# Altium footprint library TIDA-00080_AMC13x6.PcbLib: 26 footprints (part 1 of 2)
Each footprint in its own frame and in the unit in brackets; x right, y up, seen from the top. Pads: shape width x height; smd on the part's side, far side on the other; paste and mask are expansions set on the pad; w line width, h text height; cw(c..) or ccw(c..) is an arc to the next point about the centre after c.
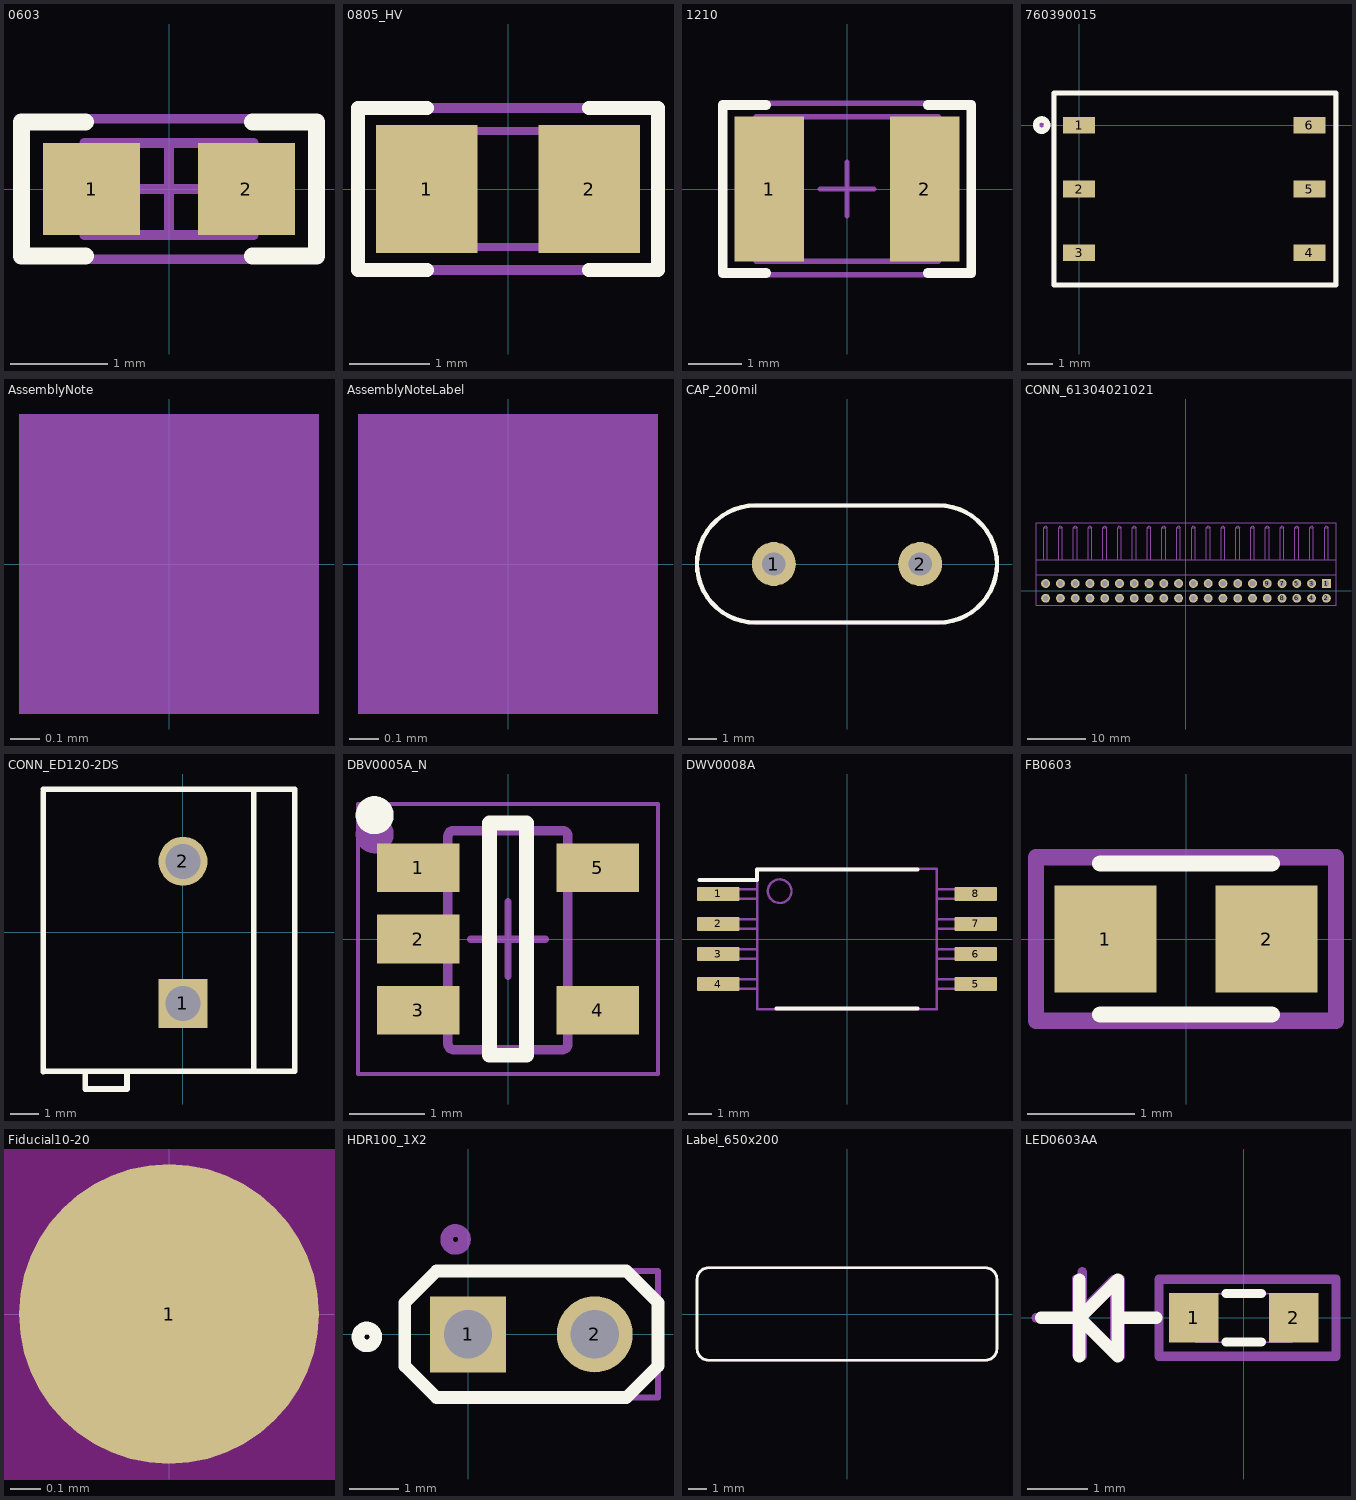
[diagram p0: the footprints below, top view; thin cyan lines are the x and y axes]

## 0603 [mm] "0603 from SM-752 data"
height 0.85
pads (2):
  rect 1x0.95 smd: 1(-0.8,0) 2(0.8,0)
Top Overlay:
  lines w0.178: -0.864,-0.691 -1.524,-0.691 -1.524,0.693 -0.864,0.693 ; 0.864,-0.691 1.524,-0.691 1.524,0.693 0.864,0.693
Mechanical 5:
  lines w0.1: -1.55,-0.725 -1.55,0.725 1.55,0.725 1.55,-0.725 -1.55,-0.725
  text ".Designator" at 0.881,0.412 h0.64
Mechanical 13:
  lines w0.1: -0.55,-0.475 -0.55,0.475 ; 0.55,-0.475 0.55,0.475 ; -0.875,-0.475 0.875,-0.475 0.875,0.475 -0.875,0.475 -0.875,-0.475
Mechanical 15:
  lines w0.1: -0.475,0 0.475,0 ; 0,-0.475 0,0.475 ; -1.55,-0.725 1.55,-0.725 1.55,0.725 -1.55,0.725 -1.55,-0.725
3D body: height 0.85, standoff 0, extent -0.874,-0.474 -0.551,0.474
3D body: height 0.85, standoff 0, extent -0.549,-0.474 0.549,0.474
3D body: height 0.85, standoff 0, extent 0.551,-0.474 0.874,0.474

## 0805_HV [mil] "0805 with 30mil clearance between pads"
height 43.31
pads (2):
  rect 50x63 smd: 1(-40,0) 2(40,0)
Top Overlay:
  lines w7: -40,-40 -74,-40 -74,0 -74,40 -40,40 ; 40,-40 74,-40 74,0 74,40 40,40
Mechanical 5:
  lines w5: -74,-40 -74,40 74,40 74,-40 -74,-40
  text ".Designator" at -25.11,-12.92 h25
Mechanical 13:
  lines w3.94: -25.59,-28.54 -25.59,28.54 ; 25.59,-28.54 25.59,28.54 ; -43.31,-28.54 43.31,-28.54 43.31,28.54 -43.31,28.54 -43.31,-28.54
3D body: height 43.31, standoff 0, extent -43.29,-28.52 -25.61,28.52
3D body: height 43.31, standoff 0, extent -25.57,-28.52 25.57,28.52
3D body: height 43.31, standoff 0, extent 25.61,-28.52 43.29,28.52

## 1210 [mm] "1210 from SM-752 data"
height 1.35
pads (2):
  rect 1.3x2.7 smd: 1(-1.45,0) 2(1.45,0)
Top Overlay:
  lines w0.178: -1.511,-1.568 -2.316,-1.568 -2.316,1.568 -1.511,1.568 ; 1.511,-1.568 2.316,-1.568 2.316,1.568 1.511,1.568
Mechanical 5:
  lines w0.1: -1.7,-1.35 -1.7,1.35 1.7,1.35 1.7,-1.35 -1.7,-1.35
  text ".Designator" at -1.03,-0.443 h0.64
Mechanical 13:
  lines w0.1: -1.2,-1.35 -1.2,1.35 ; 1.2,-1.35 1.2,1.35 ; -1.7,-1.35 1.7,-1.35 1.7,1.35 -1.7,1.35 -1.7,-1.35
Mechanical 15:
  lines w0.1: -0.5,0 0.5,0 ; 0,-0.5 0,0.5 ; -2.35,-1.6 2.35,-1.6 2.35,1.6 -2.35,1.6 -2.35,-1.6
3D body: height 1.35, standoff 0, extent 1.201,-1.349 1.699,1.349
3D body: height 1.35, standoff 0, extent -1.199,-1.349 1.199,1.349
3D body: height 1.35, standoff 0, extent -1.699,-1.349 -1.201,1.349

## 760390015 [mm]
pads (6):
  rect 1.27x0.66 smd: 1(0,0) 2(0,-2.54) 3(0,-5.08) 4(9.14,-5.08) 5(9.14,-2.54) 6(9.14,0)
Top Overlay:
  circle w0.254: c-1.494,0 r0.224
  lines w0.2: -1,-6.35 -1,1.27 10.2,1.27 10.2,-6.35 -1,-6.35
Mechanical 5:
  circle w0.254: c-1.397,0 r0.127
  lines w0.152: -1.016,-6.35 10.16,-6.35 10.16,1.27 -1.016,1.27 -1.016,-6.35
  text ".designator" at 4.007,0.303 h0.64
3D body: height 4.2, standoff 0.2, extent -1,-6.4 10.2,1.2

## AssemblyNote [mil] "Assembly Note"
Mechanical 5:
  rectangle: -20,-20 20,20
  text ".Designator" at -165,-20 h30
  text ".Comment" at 45,-20 h30

## AssemblyNoteLabel [mil] "Assembly Note for PCB Labels"
Mechanical 5:
  rectangle: -20,-20 20,20
  text ".Designator" at -165,-20 h30
  text "Install label in silkscreened box after final wash.  Text shall be 8 pt font.  Text shall be per the Label Table in the PDF schematic." at 45,-20 h30

## CAP_200mil [mil]
pads (2):
  round 60 hole 32 mask+5: 1(-100,0) 2(100,0)
Top Overlay:
  lines w6: -125,-80 cw(c-125,0) -125,80 125,80 cw(c125,0) 125,-80 -125,-80
Mechanical 5:
  lines w5: -125,-80 cw(c-125,0) -125,80 125,80 cw(c125,0) 125,-80 -125,-80
  text ".Designator" at -39,-17 h25

## CONN_61304021021 [mil]
pads (40):
  rect 60x60 hole 38: 1(952,50)
  round 60 hole 38: 2(952,-50) 3(852,50) 4(852,-50) 5(752,50) 6(752,-50) 7(652,50) 8(652,-50) 9(552,50) 10(552,-50) 11(452,50) 12(452,-50) 13(352,50) 14(352,-50) 15(252,50) 16(252,-50) 17(152,50) 18(152,-50) 19(52,50) 20(52,-50) 21(-48,50) 22(-48,-50) 23(-148,50) 24(-148,-50) 25(-248,50) 26(-248,-50) 27(-348,50) 28(-348,-50) 29(-448,50) 30(-448,-50) 31(-548,50) 32(-548,-50) 33(-648,50) 34(-648,-50) 35(-748,50) 36(-748,-50) 37(-848,50) 38(-848,-50) 39(-948,50) 40(-948,-50)
Mechanical 5:
  lines w5: -1013,109.5 1017,109.5 ; -1013,209.5 1017,209.5 ; -1013,-95.5 1017,-95.5 1017,459.5 -1013,459.5 -1013,-95.5
  text ".Designator" at 42.01,13.69 h25
Mechanical 16:
  lines w1: -960.5,210 -960.5,427.5 ; -935.5,210 -935.5,427.5 ; -860.5,210 -860.5,427.5 ; -835.5,210 -835.5,427.5 ; -760.5,210 -760.5,427.5 ; -735.5,210 -735.5,427.5 ; -660.5,210 -660.5,427.5 ; -635.5,210 -635.5,427.5 ; -560.5,210 -560.5,427.5 ; -535.5,210 -535.5,427.5 ; -460.5,210 -460.5,427.5 ; -435.5,210 -435.5,427.5 ; -360.5,210 -360.5,427.5 ; -335.5,210 -335.5,427.5 ; -260.5,210 -260.5,427.5 ; -235.5,210 -235.5,427.5 ; -160.5,210 -160.5,427.5 ; -135.5,210 -135.5,427.5 ; -60.5,210 -60.5,427.5 ; -35.5,210 -35.5,427.5 ; 39.5,210 39.5,427.5 ; 64.5,210 64.5,427.5 ; 139.5,210 139.5,427.5 ; 164.5,210 164.5,427.5 ; 239.5,210 239.5,427.5 ; 264.5,210 264.5,427.5 ; 339.5,210 339.5,427.5 ; 364.5,210 364.5,427.5 ; 439.5,210 439.5,427.5 ; 464.5,210 464.5,427.5 ; 539.5,210 539.5,427.5 ; 564.5,210 564.5,427.5 ; 639.5,210 639.5,427.5 ; 664.5,210 664.5,427.5 ; 739.5,210 739.5,427.5 ; 764.5,210 764.5,427.5 ; 839.5,210 839.5,427.5 ; 864.5,210 864.5,427.5 ; 939.5,210 939.5,427.5 ; 964.5,210 964.5,427.5 ; -960.5,427.5 -948,440 -935.5,427.5 ; -960.5,427.5 -935.5,427.5 ; -860.5,427.5 -835.5,427.5 ; -860.5,427.5 -848,440 -835.5,427.5 ; -760.5,427.5 -748,440 -735.5,427.5 ; -760.5,427.5 -735.5,427.5 ; -660.5,427.5 -648,440 -635.5,427.5 ; -660.5,427.5 -635.5,427.5 ; -560.5,427.5 -548,440 -535.5,427.5 ; -560.5,427.5 -535.5,427.5 ; -460.5,427.5 -435.5,427.5 ; -460.5,427.5 -448,440 -435.5,427.5 ; -360.5,427.5 -348,440 -335.5,427.5 ; -360.5,427.5 -335.5,427.5 ; -260.5,427.5 -248,440 -235.5,427.5 ; -260.5,427.5 -235.5,427.5 ; -160.5,427.5 -148,440 -135.5,427.5 ; -160.5,427.5 -135.5,427.5 ; -60.5,427.5 -48,440 -35.5,427.5 ; -60.5,427.5 -35.5,427.5 ; 39.5,427.5 64.5,427.5 ; 39.5,427.5 52,440 64.5,427.5 ; 139.5,427.5 164.5,427.5 ; 139.5,427.5 152,440 164.5,427.5 ; 239.5,427.5 264.5,427.5 ; 239.5,427.5 252,440 264.5,427.5 ; 339.5,427.5 352,440 364.5,427.5 ; 339.5,427.5 364.5,427.5 ; 439.5,427.5 452,440 464.5,427.5 ; 439.5,427.5 464.5,427.5 ; 539.5,427.5 552,440 564.5,427.5 ; 539.5,427.5 564.5,427.5 ; 639.5,427.5 652,440 664.5,427.5 ; 639.5,427.5 664.5,427.5 ; 739.5,427.5 752,440 764.5,427.5 ; 739.5,427.5 764.5,427.5 ; 839.5,427.5 852,440 864.5,427.5 ; 839.5,427.5 864.5,427.5 ; 939.5,427.5 952,440 964.5,427.5 ; 939.5,427.5 964.5,427.5

## CONN_ED120-2DS [mm] "ONSHORE"
height 13
pads (2):
  rect 1.75x1.75 hole 1.25: 1(0,-2.54)
  round 1.75 hole 1.25: 2(0,2.54)
Top Overlay:
  lines w0.2: -5,-4.985 -5,5.015 ; -5,-4.96 4,-4.96 ; -5,5.115 4,5.115 4,-4.885 ; -3.5,-4.96 -3.5,-5.6 -2,-5.6 -2,-4.96 ; 2.525,-4.95 2.525,5.05
Mechanical 5:
  lines w0.1: -5,-4.96 4,-4.96 ; -5,-4.885 -5,5.115 4,5.115 4,-4.885 ; -3.5,-4.96 -3.5,-5.6 -2,-5.6 -2,-4.96 ; 2.525,-4.875 2.525,5.125
  text ".Designator" at -1.27,1.118 h0.64
3D body: height 13, standoff 0, extent -5,-4.985 4,5.115
3D body: height 13.1, standoff -2.5, extent -0.496,-3.039 0.5,-2.041
3D body: height 13.1, standoff -2.5, extent -0.496,2.041 0.5,3.039
3D body: height 5.7, standoff 4.3, extent -0.85,1.846 4.15,3.24
3D body: height 5.7, standoff 4.3, extent -0.875,-3.204 4.125,-1.81
3D body: height 13, standoff 0, extent -3.5,-5.6 -2,-4.925

## DBV0005A_N [mm] "SOT23, 5-Leads, Body 2.9x1.6mm, Pitch 0.95mm, Lead Span 2.8mm, IPC Medium Density"
height 1.45
pads (5):
  rect 1.1x0.65 smd: 1(-1.2,0.95) 2(-1.2,0) 3(-1.2,-0.95) 4(1.2,-0.95) 5(1.2,0.95)
Top Overlay:
  circle w0.254: c-1.778,1.651 r0.127
  lines w0.2: -0.25,-1.55 0.25,-1.55 0.25,1.55 -0.25,1.55 -0.25,-1.55
Mechanical 5:
  circle w0.254: c-1.778,1.397 r0.127
  lines w0.127: -0.801,1.371 cw(c-0.725,1.37) -0.725,1.446 ; -0.801,1.37 -0.801,-1.399 -0.801,-1.4 ccw(c-0.725,-1.399) -0.725,-1.475 ; -0.801,1.37 -0.801,1.371 ; -0.725,-1.475 -0.725,-1.475 ; -0.725,-1.475 0.723,-1.475 0.724,-1.475 ccw(c0.723,-1.399) 0.799,-1.4 0.799,-1.399 0.799,1.37 ; -0.725,1.446 0.723,1.446 0.724,1.446 cw(c0.723,1.37) 0.799,1.371 ; -0.725,1.446 -0.725,1.446 ; 0.799,1.37 0.799,1.371 ; -1.423,-1.167 -1.199,-1.167 -1.105,-1.167 -1.088,-1.167 -0.835,-1.167 -0.801,-1.167 -0.801,-0.767 -0.835,-0.767 -1.088,-0.767 -1.105,-0.767 -1.199,-0.767 -1.423,-0.767 -1.423,-1.167 ; -1.423,-0.215 -1.199,-0.215 -1.105,-0.215 -1.088,-0.215 -0.835,-0.215 -0.801,-0.215 -0.801,0.186 -0.835,0.186 -1.088,0.186 -1.105,0.186 -1.199,0.186 -1.423,0.186 -1.423,-0.215 ; -1.423,0.738 -1.199,0.738 -1.105,0.738 -1.088,0.738 -0.835,0.738 -0.801,0.738 -0.801,1.138 -0.835,1.138 -1.088,1.138 -1.105,1.138 -1.199,1.138 -1.423,1.138 -1.423,0.738 ; 0.799,-1.167 0.799,-0.767 0.834,-0.767 1.087,-0.767 1.103,-0.767 1.198,-0.767 1.422,-0.767 1.422,-1.167 1.198,-1.167 1.103,-1.167 1.087,-1.167 0.834,-1.167 0.799,-1.167 ; 0.799,0.738 0.799,1.138 0.834,1.138 1.087,1.138 1.103,1.138 1.198,1.138 1.422,1.138 1.422,0.738 1.198,0.738 1.103,0.738 1.087,0.738 0.834,0.738 0.799,0.738
  text ".Designator" at 0.364,-1.001 h0.64
Mechanical 15:
  lines w0.05: -2,-1.8 -2,1.8 2,1.8 2,-1.8 -2,-1.8
  lines w0.1: -0.5,0 0.5,0 ; 0,-0.5 0,0.5
3D body "DBV0005AaksMF05A.stp": height 1.08, standoff -0.01, extent -1.422,-1.461 1.422,1.46

## DWV0008A [mm] "SOIC, 8-Leads, Body 5.95x7.6mm (max), Pitch 1.27mm"
height 2.8
pads (8):
  rrect17% 1.8x0.6 smd: 1(-5.45,1.905) 2(-5.45,0.635) 3(-5.45,-0.635) 4(-5.45,-1.905) 5(5.45,-1.905) 6(5.45,-0.635) 7(5.45,0.635) 8(5.45,1.905)
Top Overlay:
  lines w0.17: -6.25,2.5 -3.8,2.5 -3.8,2.95 2.975,2.95 ; -2.975,-2.95 2.975,-2.95
Mechanical 5:
  circle w0.1: c-2.85,2.025 r0.5
  lines w0.1: -3.805,-2.105 -5.8,-2.105 -5.8,-1.705 -3.805,-1.705 ; -3.805,-0.835 -5.8,-0.835 -5.8,-0.435 -3.805,-0.435 ; -3.805,0.435 -5.8,0.435 -5.8,0.835 -3.805,0.835 ; -3.805,1.705 -5.8,1.705 -5.8,2.105 -3.805,2.105 ; 3.805,-2.105 5.8,-2.105 5.8,-1.705 3.805,-1.705 ; 3.805,-0.835 5.8,-0.835 5.8,-0.435 3.805,-0.435 ; 3.805,0.435 5.8,0.435 5.8,0.835 3.805,0.835 ; 3.805,1.705 5.8,1.705 5.8,2.105 3.805,2.105 ; -3.8,-2.975 -3.8,2.975 3.8,2.975 3.8,-2.975 -3.8,-2.975
  text ".Designator" at 0.062,-0.787 h0.64
3D body "DWV0008A.stp": height 2.67, standoff -0.03, extent -5.768,-2.925 5.768,2.925

## FB0603 [mm]
height 0.95
pads (2):
  rect 0.95x1 smd: 1(-0.75,0) 2(0.75,0)
Top Overlay:
  lines w0.152: -0.8,-0.703 0.8,-0.703 ; -0.8,0.703 0.8,0.703
Mechanical 5:
  lines w0.152: -1.397,-0.762 1.397,-0.762 1.397,0.127 1.397,0.762 -1.397,0.762 -1.397,-0.762
  text ".designator" at -0.88,-0.356 h0.64
Mechanical 15:
  lines w0.025: -0.8,-0.4 -0.8,0.4 ; 0.8,-0.4 0.8,0.4
  lines w0.1: -0.8,-0.4 -0.8,0.4

## Fiducial10-20 [mm]
pads (1):
  round 1 smd paste+0 mask+0.5: 1(0,0)
Top Layer keep-out:
  circle w1.178: c0,0 r0.5

## HDR100_1X2 [mil]
pads (2):
  rect 60x60 hole 38: 1(0,0)
  round 60 hole 38: 2(100,0)
Top Overlay:
  circle w10: c-80,-2.07 r7.07
  lines w10: -50,-25 -50,25 -25,50 125,50 150,25 150,-25 125,-50 -25,-50 -50,-25
Mechanical 5:
  circle w10: c-10,75 r7.07
  lines w5: -50,-25 -25,-50 150,-50 150,50 -25,50 -50,25 -50,-25
  text ".Designator" at 76,11 h25

## Label_650x200 [mil] "Thermal Transfer Label"
height 1
pads (1):
  round 1 on Mech13: 0(0,0)
Top Overlay:
  lines w6: -325,-75 ccw(c-300,-75) -300,-100 300,-100 ccw(c300,-75) 325,-75 325,75 ccw(c300,75) 300,100 -300,100 ccw(c-300,75) -325,75 -325,-75
Mechanical 5:
  lines w5: -325,-75 ccw(c-300,-75) -300,-100 300,-100 ccw(c300,-75) 325,-75 325,75 ccw(c300,75) 300,100 -300,100 ccw(c-300,75) -325,75 -325,-75
  text ".Designator" at 65,25 h25
3D body: height 1, standoff 0, extent -325.02,-100.02 325.02,100.02

## LED0603AA [mil]
height 35.43
pads (2):
  rect 32x32 smd: 1(-32.48,0) 2(32.48,0)
Top Overlay:
  lines w6: -11.42,-15.75 11.42,-15.75 ; -11.42,15.75 11.42,15.75
  lines w8: -131.79,-0.04 -106.79,-0.04 ; -106.79,-25.04 -106.79,24.96 ; -81.79,-0.04 -56.79,-0.04 ; -106.79,-0.04 -81.79,-25.04 -81.79,24.96 -106.79,-0.04
Mechanical 5:
  lines w6: -135,0 -105,0 ; -105,-25 -105,30 ; -80,0 -55,0 ; -105,0 -80,25 -80,-25 -105,0 ; -55,-25 60,-25 60,25 -55,25 -55,-25
  text ".designator" at 25,15 h25
Mechanical 15:
  lines w1: -31.5,-15.75 -31.5,15.75 31.5,15.75 31.5,-15.75 -31.5,-15.75
  lines w3.94: -134.79,0.96 -109.79,0.96 ; -109.79,-24.04 -109.79,25.96 ; -84.79,0.96 -59.79,0.96 ; -109.79,0.96 -84.79,-24.04 -84.79,25.96 -109.79,0.96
